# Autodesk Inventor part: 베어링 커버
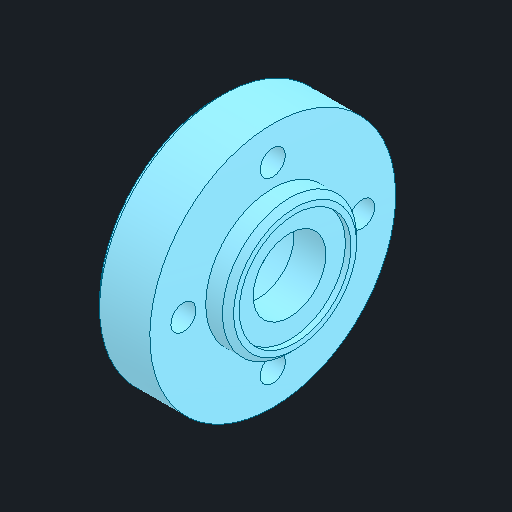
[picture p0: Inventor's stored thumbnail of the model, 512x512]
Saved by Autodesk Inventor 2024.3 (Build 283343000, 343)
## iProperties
Created: 2024-05
Part Number: 베어링 커버
Material: 강철, 연강
Document SubType Name: Modeling
Designer: MyPc
Density: 7.85 g/cm^3
Appearance: 기본값
Author: jhkim
Sending System: Autodesk Inventor 2025
Preprocessor: ST-DEVELOPER v20
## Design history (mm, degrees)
node "베어링 커버1"
node "솔리드2"
node "솔리드1"
